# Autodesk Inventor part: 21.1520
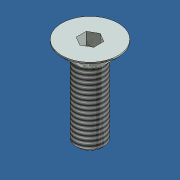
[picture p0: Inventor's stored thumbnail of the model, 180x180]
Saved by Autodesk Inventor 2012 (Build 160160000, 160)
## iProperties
Created: 2006-12
Part Number: 21.1520
Material: Steel, Mild
Description: M8x25 C'SUNK
Document SubType Name: Modeling
Standard: DIN 7991
Designer: Andy Moles
Standards Organization: DIN
Language: en-US
Size Designation: M8x25
Categories: <MemberInstance Version="R10.0.0"><Categories><Category DisplayName="Fasteners" InternalName="e4da775c-781d-43d5-af7c-5136215cf5a6" Mnemonic="FSTN"><Category Di
Density: 7.86 g/cm^3
Mass: 11.8273 g
Surface Area: 10.5283 cm^2
Volume: 1.50474 cm^3
Vendor: S
Author: Andy Moles
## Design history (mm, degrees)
node "Sketch1"
node "WorkPoint1"
sketch "Sketch2"
  geometry: L1 (-4, -25)-(0, -25); L2 (-4, -4.4)-(-4, -25); L3 (-8, -0.4)-(-4, -4.4); L4 (-8, 0)-(-8, -0.4); L5 (0, 0)-(-8, 0); L6 (0, -25)-(0, 0); L7 (0, -25)-(0, 0); L8 (0, -27.5)-(0, 7.5) reference; L9 (0.8, 0)-(-10.4, 0) reference
  constraints: 14 end point, 3 vertical, 2 horizontal
  dimensions: "d1" = 45 deg angle of L3 L6; "d3" = 8 distance of L5.start L4.start (= 0.5 x dk); "d5" = 4 distance of L1.start L1.end (= 0.5 x NND); "d7" = 25 distance of L1.end L5.start (= NLG); "ParC" = 0.4 distance of L4.start L3.start; "d22" = 0 distance between parallel lines of L8 L6; "d23" = 0 distance between parallel lines of L9 L5
fillet "Fillet1" dims "d18" = 0.5 (= r)
chamfer "Chamfer1" distance "d19" = 0.625 (= 0.5 x PTC); stored, may be unused: angle "d20" = 45 deg, second distance "d39" = 0.625 (= 0.5 x PTC)
node "MSC_A1"
node "MSC_PF1"
node "MSC_PT1"
body "Solid1"
revolve "Revolution1" stored, may be unused: angle "d8" = 360 deg
sketch "Sketch3"
  geometry: L1 (-2.5, 1.443)-(-2.5, -1.443); L2 (0, 2.887)-(-2.5, 1.443); L3 (2.5, 1.443)-(0, 2.887); L4 (2.5, -1.443)-(2.5, 1.443); L5 (0, -2.887)-(2.5, -1.443); L6 (-2.5, -1.443)-(0, -2.887); C1 r 2.5 at (0, 0); C2 r 4 at (0, 0) reference
  constraints: 12 end point, 6 tangent, 2 parallel, 2 vertical, 1 centre point, 1 concentric
  dimensions: "d11" = 5 diameter of C1 (= ParS); "d13" = 120 deg angle of L1 L2; "d15" = 120 deg angle of L6 L1
extrude "Extrusion1" cut sketch "Sketch3" distance "d16" = 3.5 (= ParT); taper "d17" = 0 deg
thread "Thread1" dims "d35" = 0, "b" = 21
other parameters: "NND" = 8 [user parameter; used in 2 equation terms], "PTC" = 1.25 [user parameter; used in 2 equation terms], "dk" = 16 [user parameter; used in 1 equation term], "ParK" = 4.4 [user parameter], "ParS" = 5 [user parameter; used in 1 equation term], "ParT" = 3.5 [user parameter; used in 1 equation term], "r" = 0.5 [user parameter; used in 1 equation term], "NLG" = 25 [user parameter; used in 1 equation term], "d0" = 45 deg (derived), "d2" = 3 (derived), "d4" = 1.5 (derived), "d6" = 8 (derived), "d9" = 0, "d10" = 2 (derived), "d12" = 120 deg (derived), "d14" = 120 deg (derived), "d37" = 0, "d38" = 0, "d40" = 0, "d41" = 0, "d42" = 0, "THREADDIA" = 8 (= NND) [user parameter]
